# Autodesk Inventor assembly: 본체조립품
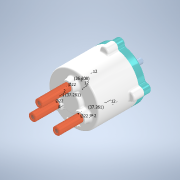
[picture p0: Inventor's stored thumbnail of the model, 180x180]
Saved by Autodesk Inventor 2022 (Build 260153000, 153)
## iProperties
Created: 2021-07
Part Number: 본체조립품
Document SubType Name: Assembly
Designer: micke
Author: micke
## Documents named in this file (14)
- C:\Users\micke\Desktop\610708V1008\본체조립품.iam
- C:\Users\micke\Desktop\610708V1008\본체.ipt
- C:\Users\micke\Desktop\610708V1008\가변스프링1.ipt
- C:\Users\micke\Desktop\610708V1008\가변스프링2.ipt
- C:\Users\micke\Desktop\610708V1008\가변스프링3.ipt
- C:\Users\micke\Desktop\610708V1008\멈춤링 10 x 1.ipt
- C:\Users\micke\Desktop\610708V1008\멈춤링 22 x 1.2.ipt
- C:\Users\micke\Desktop\610708V1008\메인 축.ipt
- C:\Users\micke\Desktop\610708V1008\베어링 NA 4900.ipt
- C:\Users\micke\Desktop\610708V1008\볼트 M5.ipt
- C:\Users\micke\Desktop\610708V1008\슬라이드 축.ipt
- C:\Users\micke\Desktop\610708V1008\오일실.ipt
- C:\Users\micke\Desktop\610708V1008\커버.ipt
- C:\Users\micke\Desktop\610708V1008\판캠.ipt
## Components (3 placed, 3 different names)
1. 가변스프링1:1
2. 가변스프링2:1
3. 가변스프링3:1
